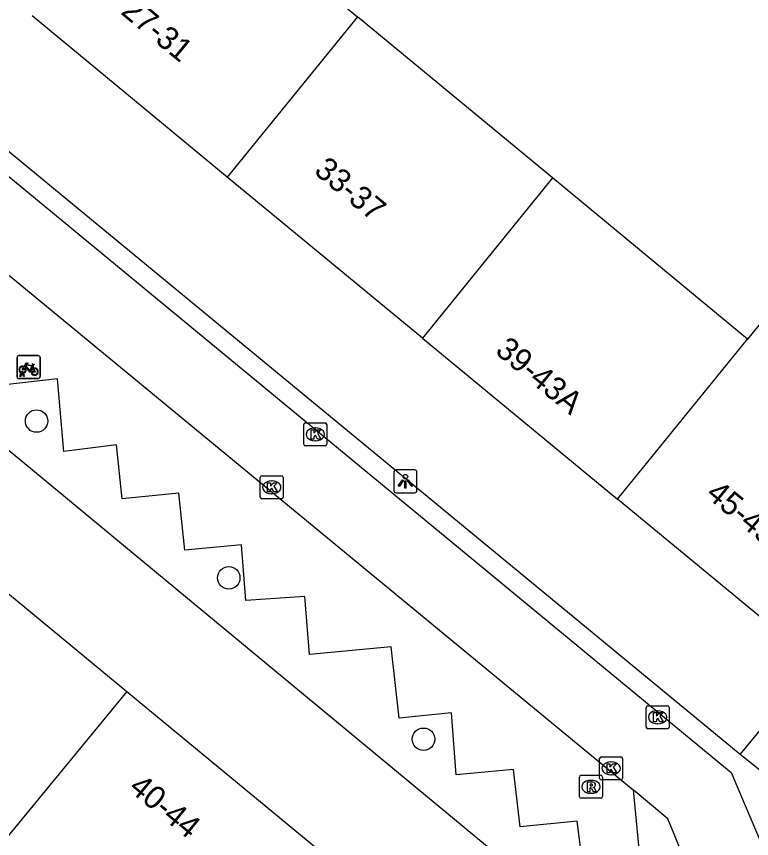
# Model space of a CAD drawing. Extents: x 162074 to 163034, y 381824 to 382557.
# Drawn here: x 162417.07 to 162449.04, y 382070.34 to 382106.09 of the extents above; entities that cross this region are included whole.
import ezdxf

# ---------------------------------------------------------------- set-up
doc = ezdxf.new("R2010")
doc.units = 0
for name, color, linetype in [('IMGEO_Boom', 7, 'Continuous'), ('IMGEO_Fietsenrek', 7, 'Continuous'), ('IMGEO_Kolk', 7, 'Continuous'), ('IMGEO_Lichtpunt', 7, 'Continuous'), ('IMGEO_Pand', 7, 'Continuous'), ('IMGEO_Pand_nummerreeks', 7, 'Continuous'), ('IMGEO_Rijbaan_lokaal_open', 7, 'Continuous'), ('IMGEO_Rioolput', 7, 'Continuous'), ('IMGEO_Voetpad_open', 7, 'Continuous')]:
    doc.layers.add(name, color=color, linetype=linetype)

msp = doc.modelspace()

# ---------------------------------------------------------------- linework, layer by layer
at = {"layer": 'IMGEO_Boom'}
for centre in [(162417.947, 382088.497), (162426.302, 382081.68), (162434.771, 382074.66)]:
    msp.add_circle(centre, 0.489, dxfattribs=at)
at = {"layer": 'IMGEO_Fietsenrek'}
for p, q in [((162417.17, 382091.342), (162418.011, 382091.342)), ((162418.011, 382091.342), (162417.17, 382091.342)), ((162417.095, 382090.417), (162417.095, 382091.258)), ((162417.095, 382091.258), (162417.095, 382090.417)), ((162418.095, 382091.267), (162418.095, 382090.426)), ((162418.095, 382090.426), (162418.095, 382091.267)), ((162417.222, 382090.426), (162417.261, 382090.586)), ((162417.291, 382090.574), (162417.256, 382090.426)), ((162417.333, 382090.598), (162417.332, 382090.602)), ((162417.374, 382090.426), (162417.34, 382090.568)), ((162417.364, 382090.609), (162417.365, 382090.602)), ((162417.372, 382090.572), (162417.407, 382090.426)), ((162417.782, 382090.891), (162417.818, 382090.796)), ((162418.02, 382090.342), (162417.179, 382090.342)), ((162417.179, 382090.342), (162418.02, 382090.342)), ((162417.256, 382090.426), (162417.222, 382090.426)), ((162417.407, 382090.426), (162417.374, 382090.426))]:
    msp.add_line(p, q, dxfattribs=at)
for points in [[(162417.408, 382090.868), (162417.503, 382091.032), (162417.589, 382091.018), (162417.591, 382091.009), (162417.535, 382090.998), (162417.508, 382090.953), (162417.764, 382090.912)], [(162417.751, 382090.887), (162417.494, 382090.928), (162417.477, 382090.899), (162417.644, 382090.679), (162417.751, 382090.887)], [(162417.764, 382090.912), (162417.789, 382090.961), (162417.783, 382090.965), (162417.76, 382090.969), (162417.748, 382090.976), (162417.747, 382090.979), (162417.749, 382090.984), (162417.844, 382090.969), (162417.846, 382090.959), (162417.836, 382090.946), (162417.824, 382090.94), (162417.81, 382090.946), (162417.782, 382090.891)], [(162417.429, 382090.816), (162417.377, 382090.726), (162417.337, 382090.701), (162417.338, 382090.748), (162417.393, 382090.842)], [(162417.704, 382090.624), (162417.654, 382090.624), (162417.463, 382090.875), (162417.444, 382090.843)], [(162417.799, 382090.789), (162417.769, 382090.866), (162417.66, 382090.648), (162417.703, 382090.648)], [(162417.733, 382090.648), (162417.853, 382090.647), (162417.809, 382090.761)], [(162417.829, 382090.768), (162417.884, 382090.623), (162417.734, 382090.623)]]:
    msp.add_lwpolyline(points, dxfattribs=at)
for centre, radius, start, end in [((162417.173, 382091.264), 0.0779, 92.4484, 184.2845), ((162417.173, 382091.264), 0.0779, 92.4484, 184.2845), ((162418.017, 382091.264), 0.0779, 2.4484, 94.2845), ((162418.017, 382091.264), 0.0779, 2.4484, 94.2845), ((162417.335, 382090.727), 0.159, 62.6766, 242.1369), ((162417.335, 382090.727), 0.129, 63.3192, 238.903), ((162417.315, 382090.598), 0.0499, 12.8025, 158.6934), ((162417.335, 382090.727), 0.159, 253.9967, 271.7867), ((162417.315, 382090.598), 0.0174, 12.8025, 163.4502), ((162417.335, 382090.727), 0.129, 253.415, 269.0204), ((162417.335, 382090.727), 0.129, 283.6043, 43.4302), ((162417.335, 382090.727), 0.159, 283.5766, 46.6042), ((162417.862, 382090.643), 0.159, 113.3408, 178.3217), ((162417.862, 382090.643), 0.159, 187.0065, 105.7708), ((162417.862, 382090.643), 0.129, 113.923, 177.9556), ((162417.862, 382090.643), 0.129, 188.6715, 104.5883), ((162417.173, 382090.42), 0.0779, 182.4484, 274.2845), ((162417.173, 382090.42), 0.0779, 182.4484, 274.2845), ((162418.017, 382090.42), 0.0779, 272.4484, 4.2845), ((162418.017, 382090.42), 0.0779, 272.4484, 4.2845)]:
    msp.add_arc(centre, radius, start, end, dxfattribs=at)
at = {"layer": 'IMGEO_Kolk'}
for p, q in [((162429.64, 382088.415), (162430.492, 382088.415)), ((162429.565, 382087.489), (162429.565, 382088.341)), ((162430.053, 382088.195), (162430.078, 382088.195)), ((162430.566, 382088.341), (162430.566, 382087.489)), ((162430.492, 382087.415), (162429.64, 382087.415)), ((162430.076, 382087.635), (162430.051, 382087.635)), ((162427.671, 382085.19), (162427.671, 382086.042)), ((162427.746, 382086.116), (162428.598, 382086.116)), ((162428.672, 382086.042), (162428.672, 382085.19)), ((162428.159, 382085.896), (162428.184, 382085.896)), ((162428.182, 382085.336), (162428.157, 382085.336)), ((162428.598, 382085.116), (162427.746, 382085.116)), ((162444.453, 382075.191), (162444.453, 382076.043)), ((162444.528, 382076.117), (162445.38, 382076.117)), ((162445.454, 382076.043), (162445.454, 382075.191)), ((162444.941, 382075.897), (162444.966, 382075.897)), ((162444.964, 382075.337), (162444.939, 382075.337)), ((162445.38, 382075.117), (162444.528, 382075.117)), ((162442.43, 382072.968), (162442.43, 382073.82)), ((162442.505, 382073.894), (162443.357, 382073.894)), ((162443.431, 382073.82), (162443.431, 382072.968)), ((162442.918, 382073.674), (162442.943, 382073.674)), ((162442.941, 382073.114), (162442.916, 382073.114)), ((162443.357, 382072.894), (162442.505, 382072.894))]:
    msp.add_line(p, q, dxfattribs=at)
for points in [[(162429.64, 382088.415), (162430.492, 382088.415)], [(162429.565, 382087.489), (162429.565, 382088.341)], [(162429.886, 382088.115), (162430.009, 382088.115), (162430.009, 382087.964), (162430.139, 382088.115), (162430.303, 382088.115), (162430.157, 382087.964), (162430.31, 382087.715), (162430.158, 382087.715), (162430.073, 382087.879), (162430.009, 382087.812), (162430.009, 382087.715), (162429.886, 382087.715), (162429.886, 382088.115)], [(162430.566, 382088.341), (162430.566, 382087.489)], [(162430.492, 382087.415), (162429.64, 382087.415)], [(162427.671, 382085.19), (162427.671, 382086.042)], [(162427.746, 382086.116), (162428.598, 382086.116)], [(162428.672, 382086.042), (162428.672, 382085.19)], [(162427.992, 382085.816), (162428.115, 382085.816), (162428.115, 382085.665), (162428.245, 382085.816), (162428.409, 382085.816), (162428.263, 382085.665), (162428.416, 382085.416), (162428.264, 382085.416), (162428.179, 382085.58), (162428.115, 382085.513), (162428.115, 382085.416), (162427.992, 382085.416), (162427.992, 382085.816)], [(162428.598, 382085.116), (162427.746, 382085.116)], [(162444.453, 382075.191), (162444.453, 382076.043)], [(162444.528, 382076.117), (162445.38, 382076.117)], [(162445.454, 382076.043), (162445.454, 382075.191)], [(162444.774, 382075.817), (162444.897, 382075.817), (162444.897, 382075.666), (162445.027, 382075.817), (162445.191, 382075.817), (162445.045, 382075.666), (162445.198, 382075.417), (162445.046, 382075.417), (162444.961, 382075.581), (162444.897, 382075.514), (162444.897, 382075.417), (162444.774, 382075.417), (162444.774, 382075.817)], [(162445.38, 382075.117), (162444.528, 382075.117)], [(162442.43, 382072.968), (162442.43, 382073.82)], [(162442.505, 382073.894), (162443.357, 382073.894)], [(162443.431, 382073.82), (162443.431, 382072.968)], [(162442.751, 382073.594), (162442.874, 382073.594), (162442.874, 382073.443), (162443.004, 382073.594), (162443.168, 382073.594), (162443.022, 382073.443), (162443.175, 382073.194), (162443.023, 382073.194), (162442.938, 382073.358), (162442.874, 382073.291), (162442.874, 382073.194), (162442.751, 382073.194), (162442.751, 382073.594)], [(162443.357, 382072.894), (162442.505, 382072.894)]]:
    msp.add_lwpolyline(points, dxfattribs=at)
for centre, start, end in [((162429.642, 382088.339), 91.552, 178.448), ((162429.642, 382088.339), 91.552, 178.448), ((162430.49, 382088.339), 1.552, 88.448), ((162430.49, 382088.339), 1.552, 88.448), ((162429.642, 382087.491), 181.552, 268.448), ((162429.642, 382087.491), 181.552, 268.448), ((162430.49, 382087.491), 271.552, 358.448), ((162430.49, 382087.491), 271.552, 358.448), ((162427.748, 382086.04), 91.552, 178.448), ((162427.748, 382086.04), 91.552, 178.448), ((162428.596, 382086.04), 1.552, 88.448), ((162428.596, 382086.04), 1.552, 88.448), ((162427.748, 382085.192), 181.552, 268.448), ((162427.748, 382085.192), 181.552, 268.448), ((162428.596, 382085.192), 271.552, 358.448), ((162428.596, 382085.192), 271.552, 358.448), ((162444.53, 382076.041), 91.552, 178.448), ((162444.53, 382076.041), 91.552, 178.448), ((162445.378, 382076.041), 1.552, 88.448), ((162445.378, 382076.041), 1.552, 88.448), ((162444.53, 382075.193), 181.552, 268.448), ((162444.53, 382075.193), 181.552, 268.448), ((162445.378, 382075.193), 271.552, 358.448), ((162445.378, 382075.193), 271.552, 358.448), ((162442.507, 382073.818), 91.552, 178.448), ((162442.507, 382073.818), 91.552, 178.448), ((162443.355, 382073.818), 1.552, 88.448), ((162443.355, 382073.818), 1.552, 88.448), ((162442.507, 382072.97), 181.552, 268.448), ((162442.507, 382072.97), 181.552, 268.448), ((162443.355, 382072.97), 271.552, 358.448), ((162443.355, 382072.97), 271.552, 358.448)]:
    msp.add_arc(centre, 0.0765, start, end, dxfattribs=at)
for centre, major_axis, ratio, start_param, end_param in [((162430.052, 382087.915), (-0.387, 0.002), 0.722429, 4.712389, 7.853982), ((162430.077, 382087.915), (-0.39, 0.002), 0.717154, 1.570796, 4.712389), ((162428.158, 382085.616), (-0.387, 0.002), 0.722429, 4.712389, 7.853982), ((162428.183, 382085.616), (-0.39, 0.002), 0.717154, 1.570796, 4.712389), ((162444.94, 382075.617), (-0.387, 0.002), 0.722429, 4.712389, 7.853982), ((162444.965, 382075.617), (-0.39, 0.002), 0.717154, 1.570796, 4.712389), ((162442.917, 382073.394), (-0.387, 0.002), 0.722429, 4.712389, 7.853982), ((162442.942, 382073.394), (-0.39, 0.002), 0.717154, 1.570796, 4.712389)]:
    msp.add_ellipse(centre, major_axis=major_axis, ratio=ratio, start_param=start_param, end_param=end_param, dxfattribs=at)
at = {"layer": 'IMGEO_Lichtpunt'}
for p, q in [((162433.486, 382086.279), (162433.486, 382085.472)), ((162433.486, 382086.279), (162433.486, 382085.472)), ((162434.388, 382086.374), (162433.58, 382086.374)), ((162434.388, 382086.374), (162433.58, 382086.374)), ((162434.482, 382085.472), (162434.482, 382086.279)), ((162434.482, 382085.472), (162434.482, 382086.279)), ((162433.58, 382085.378), (162434.388, 382085.378)), ((162433.58, 382085.378), (162434.388, 382085.378))]:
    msp.add_line(p, q, dxfattribs=at)
for points in [[(162433.86, 382085.943), (162433.899, 382085.915), (162433.711, 382085.653), (162433.673, 382085.68), (162433.86, 382085.943)], [(162434.072, 382085.915), (162434.11, 382085.942), (162434.297, 382085.68), (162434.258, 382085.652), (162434.072, 382085.915)], [(162433.962, 382085.895), (162434.009, 382085.895), (162434.009, 382085.573), (162433.962, 382085.573), (162433.962, 382085.895)]]:
    msp.add_lwpolyline(points, dxfattribs=at)
msp.add_circle((162433.985, 382086.077), 0.0994, dxfattribs=at)
for centre, start, end in [((162433.58, 382086.279), 90, 180), ((162433.58, 382086.279), 90, 180), ((162434.388, 382086.279), 0, 90), ((162434.388, 382086.279), 0, 90), ((162433.58, 382085.472), 180, 270), ((162433.58, 382085.472), 180, 270), ((162434.388, 382085.472), 270, 0), ((162434.388, 382085.472), 270, 360)]:
    msp.add_arc(centre, 0.0946, start, end, dxfattribs=at)
at = {"layer": 'IMGEO_Pand'}
for points in [[(162423.413, 382113.07), (162423.685, 382112.846), (162430.242, 382120.791), (162433.377, 382118.204), (162426.82, 382110.258), (162431.897, 382106.068)], [(162426.235, 382099.105), (162417.75, 382106.108)], [(162431.897, 382106.068), (162426.235, 382099.105)], [(162440.381, 382099.065), (162431.897, 382106.068)], [(162457.546, 382084.897), (162457.449, 382084.977), (162458.753, 382086.556), (162453.876, 382090.581), (162460.128, 382098.157), (162456.35, 382101.275), (162448.864, 382092.063)], [(162434.72, 382092.101), (162426.235, 382099.105)], [(162440.381, 382099.065), (162434.72, 382092.101)], [(162448.864, 382092.063), (162440.381, 382099.065)], [(162434.72, 382092.101), (162443.204, 382085.098)], [(162443.204, 382085.098), (162448.864, 382092.063)], [(162451.833, 382077.976), (162443.204, 382085.098)], [(162413.399, 382083.717), (162421.871, 382076.736)], [(162421.871, 382076.736), (162416.1, 382069.733)], [(162421.871, 382076.736), (162430.342, 382069.755)]]:
    msp.add_lwpolyline(points, dxfattribs=at)
at = {"layer": 'IMGEO_Rijbaan_lokaal_open'}
for points in [[(162374.57, 382130.393), (162375.036, 382129.973), (162382.822, 382127.114), (162448.153, 382073.217), (162450.473, 382067.754), (162451.851, 382066.605)], [(162383.272, 382122.429), (162443.882, 382072.46)], [(162449.709, 382064.013), (162447.637, 382065.739), (162445.4, 382071.193), (162443.882, 382072.46)]]:
    msp.add_lwpolyline(points, dxfattribs=at)
at = {"layer": 'IMGEO_Rioolput'}
for p, q in [((162441.627, 382073.092), (162442.479, 382073.092)), ((162441.552, 382072.166), (162441.552, 382073.018)), ((162442.04, 382072.872), (162442.065, 382072.872)), ((162442.553, 382073.018), (162442.553, 382072.166)), ((162442.479, 382072.092), (162441.627, 382072.092)), ((162442.063, 382072.312), (162442.038, 382072.312))]:
    msp.add_line(p, q, dxfattribs=at)
for points in [[(162441.627, 382073.092), (162442.479, 382073.092)], [(162441.552, 382072.166), (162441.552, 382073.018)], [(162442.141, 382072.79), (162441.889, 382072.792), (162441.889, 382072.392)], [(162442.067, 382072.711), (162442.013, 382072.711), (162442.013, 382072.63)], [(162442.553, 382073.018), (162442.553, 382072.166)], [(162441.889, 382072.392), (162442.013, 382072.392), (162442.013, 382072.554), (162442.024, 382072.554)], [(162442.013, 382072.63), (162442.065, 382072.63)], [(162442.071, 382072.525), (162442.142, 382072.392), (162442.282, 382072.392), (162442.217, 382072.518)], [(162442.479, 382072.092), (162441.627, 382072.092)]]:
    msp.add_lwpolyline(points, dxfattribs=at)
for centre, radius, start, end in [((162441.629, 382073.016), 0.0765, 91.552, 178.448), ((162441.629, 382073.016), 0.0765, 91.552, 178.448), ((162442.477, 382073.016), 0.0765, 1.552, 88.448), ((162442.477, 382073.016), 0.0765, 1.552, 88.448), ((162442.073, 382072.615), 0.0964, 77.0061, 93.1865), ((162442.087, 382072.672), 0.0378, 276.6634, 79.6772), ((162442.14, 382072.68), 0.109, 350.3612, 89.416), ((162442.023, 382072.501), 0.0533, 26.0293, 88.6989), ((162442.049, 382072.819), 0.19, 274.7715, 282.9687), ((162442.138, 382072.68), 0.112, 277.5842, 350.9817), ((162442.122, 382072.465), 0.108, 29.5134, 73.7905), ((162441.629, 382072.168), 0.0765, 181.552, 268.448), ((162441.629, 382072.168), 0.0765, 181.552, 268.448), ((162442.477, 382072.168), 0.0765, 271.552, 358.448), ((162442.477, 382072.168), 0.0765, 271.552, 358.448)]:
    msp.add_arc(centre, radius, start, end, dxfattribs=at)
for centre, major_axis, ratio, start_param, end_param in [((162442.039, 382072.592), (-0.387, 0.002), 0.722429, 4.712389, 7.853982), ((162442.064, 382072.592), (-0.39, 0.002), 0.717154, 1.570796, 4.712389)]:
    msp.add_ellipse(centre, major_axis=major_axis, ratio=ratio, start_param=start_param, end_param=end_param, dxfattribs=at)
at = {"layer": 'IMGEO_Voetpad_open'}
for points in [[(162448.544, 382073.992), (162380.395, 382130.153)], [(162442.197, 382066.248), (162438.394, 382069.293), (162374.058, 382122.534)], [(162441.755, 382068.708), (162441.451, 382071.1), (162438.969, 382070.857), (162438.688, 382073.348), (162436.19, 382073.11), (162435.989, 382075.816), (162433.706, 382075.579), (162433.368, 382078.685), (162429.813, 382078.35), (162429.611, 382080.866), (162427.045, 382080.693), (162426.86, 382083.109), (162424.388, 382082.888), (162424.127, 382085.367), (162421.662, 382085.114), (162421.425, 382087.455), (162419.131, 382087.175), (162418.85, 382090.328), (162415.534, 382089.952)], [(162448.544, 382073.992), (162451.833, 382077.976)], [(162453.791, 382069.764), (162453.132, 382070.292), (162452.152, 382071.11), (162448.681, 382073.879), (162448.544, 382073.992)], [(162443.882, 382072.46), (162444.221, 382068.98)]]:
    msp.add_lwpolyline(points, dxfattribs=at)

# ---------------------------------------------------------------- texts
at = {"layer": 'IMGEO_Pand_nummerreeks'}
for s, rotation, p in [('27-31', 320.4659, (162421.564, 382106.228)), ('33-37', 320.4638, (162429.964, 382099.294)), ('39-43A', 320.4602, (162437.84, 382091.471)), ('45-49', 320.4659, (162447.002, 382085.231)), ('40-44', 320.5113, (162421.902, 382072.461))]:
    msp.add_text(s, height=1, rotation=rotation, dxfattribs=at).set_placement(p)

doc.saveas('drawing.dxf')
